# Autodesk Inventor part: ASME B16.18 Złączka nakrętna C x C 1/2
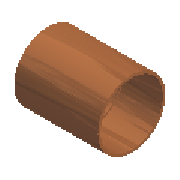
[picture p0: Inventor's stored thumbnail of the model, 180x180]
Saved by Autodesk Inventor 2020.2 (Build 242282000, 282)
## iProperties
Manager: www.cadconsulting.pl
Company: Fabian Stasiak CAD Consulting
Created: 2014-02
Part Number: ASME B16.18 Złączka nakrętna C x C 1/2
Material: Miedź, odlew
Description: Złączka nakrętna C x C odlewana ze stopu miedzi, lutowana na wcisk
Document SubType Name: Modeling
Standard: ASME B16.18
Designer: F.Stasiak
Standard Revision: 2001
Standards Organization: ANSI
Language: pl-PL
Size Designation: 1/2
Categories: <MemberInstance><Categories><Category DisplayName="Rury cienko- i grubościenne" InternalName="4347fa0f-2144-441d-94cd-e3e15c92b736" Mnemonic="TUBEANDPIPE"><Cate
Density: 1 g/cm^3
Appearance: Miedź - satynowa
Catalog Web Link: www.expertbooks.pl
IsCustomPart: 0
NAME: PIPING: ASME B16.18 Coupling C x C
DATA: <meta><inlinegroups number="1" deflen="7.2898"></inlinegroups><connections number="2"></connections><angles><a>3.14159265358979</a></angles></meta>
Author: F.Stasiak
Subject: Zbiór ćwiczeń. Autodesk Inventor 2020. Kurs Professional
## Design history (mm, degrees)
sketch "Sketch1"
  geometry: L1 (0, 0)-(-28.448, 0); L2 (0, 0)-(0, 7.963); L3 (-28.448, 0)-(-28.448, 7.963); L4 (0, 7.963)-(0, 9.233); L5 (0, 9.233)-(-28.448, 9.233); L6 (-28.448, 9.233)-(-28.448, 7.963); L7 (-15.748, 7.963)-(-15.748, 6.947); L8 (-15.748, 7.963)-(-28.448, 7.963); L9 (-15.748, 6.947)-(-12.7, 6.947); L10 (-12.7, 6.947)-(-12.7, 7.963); L11 (-12.7, 7.963)-(0, 7.963); 1 further point
  constraints: 22 end point, 5 parallel, 5 perpendicular, 1 coincident, 1 collinear, 1 horizontal
  dimensions: "d0" = 12.7 horizontal distance of L9.end L1.start (= G); "d1" = 12.7 horizontal distance of L3.end L7.end (= G); "d2" = 3.048 distance of L7.end L9.end (= M); "d3" = 1.27 distance of L2.end L4.end (= R); "d4" = 2.286 vertical distance of L9.end L4.end (= T); "d5" = 7.9629 distance of L1.start L2.end (= 0.5 x ID)
revolve "Revolve1" sketch "Sketch1" stored, may be unused: angle "d7" = 90 deg
workaxis "Work Axis1"
workpoint "Work Point1"
workpoint "Work Point2"
workaxis "Work Axis2"
workpoint "Work Point3"
workpoint "Work Point4"
body "Solid1"
other parameters: "M" = 3.048 [user parameter; used in 1 equation term], "G" = 12.7 [user parameter; used in 2 equation terms], "R" = 1.27 [user parameter; used in 1 equation term], "T" = 2.286 [user parameter; used in 1 equation term], "ID" = 15.9258 [user parameter; used in 1 equation term], "Size_Designation" = 5 [user parameter]
